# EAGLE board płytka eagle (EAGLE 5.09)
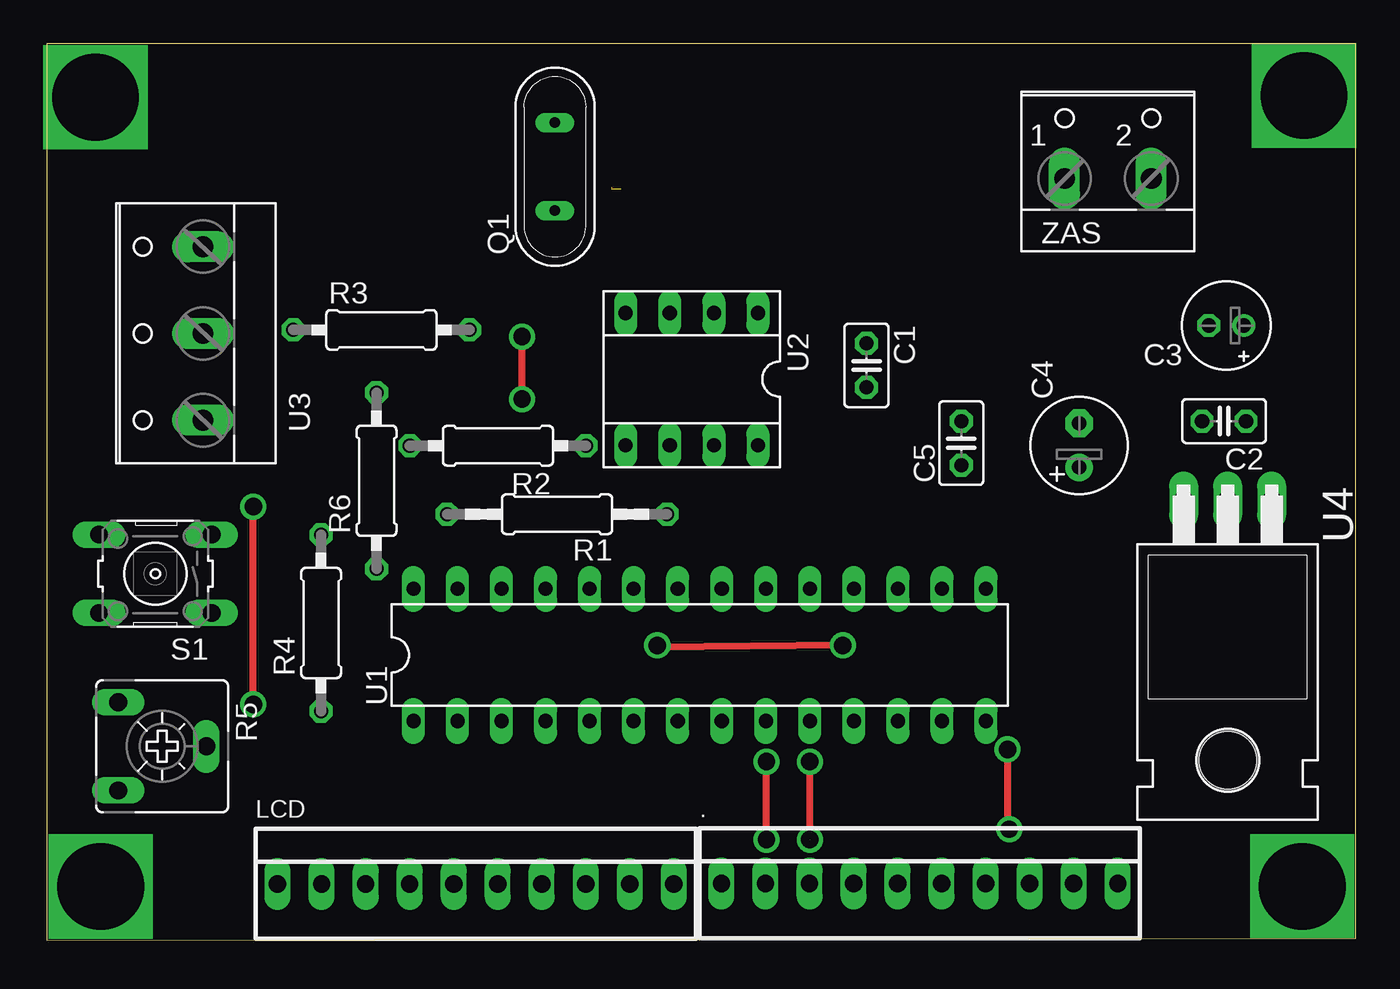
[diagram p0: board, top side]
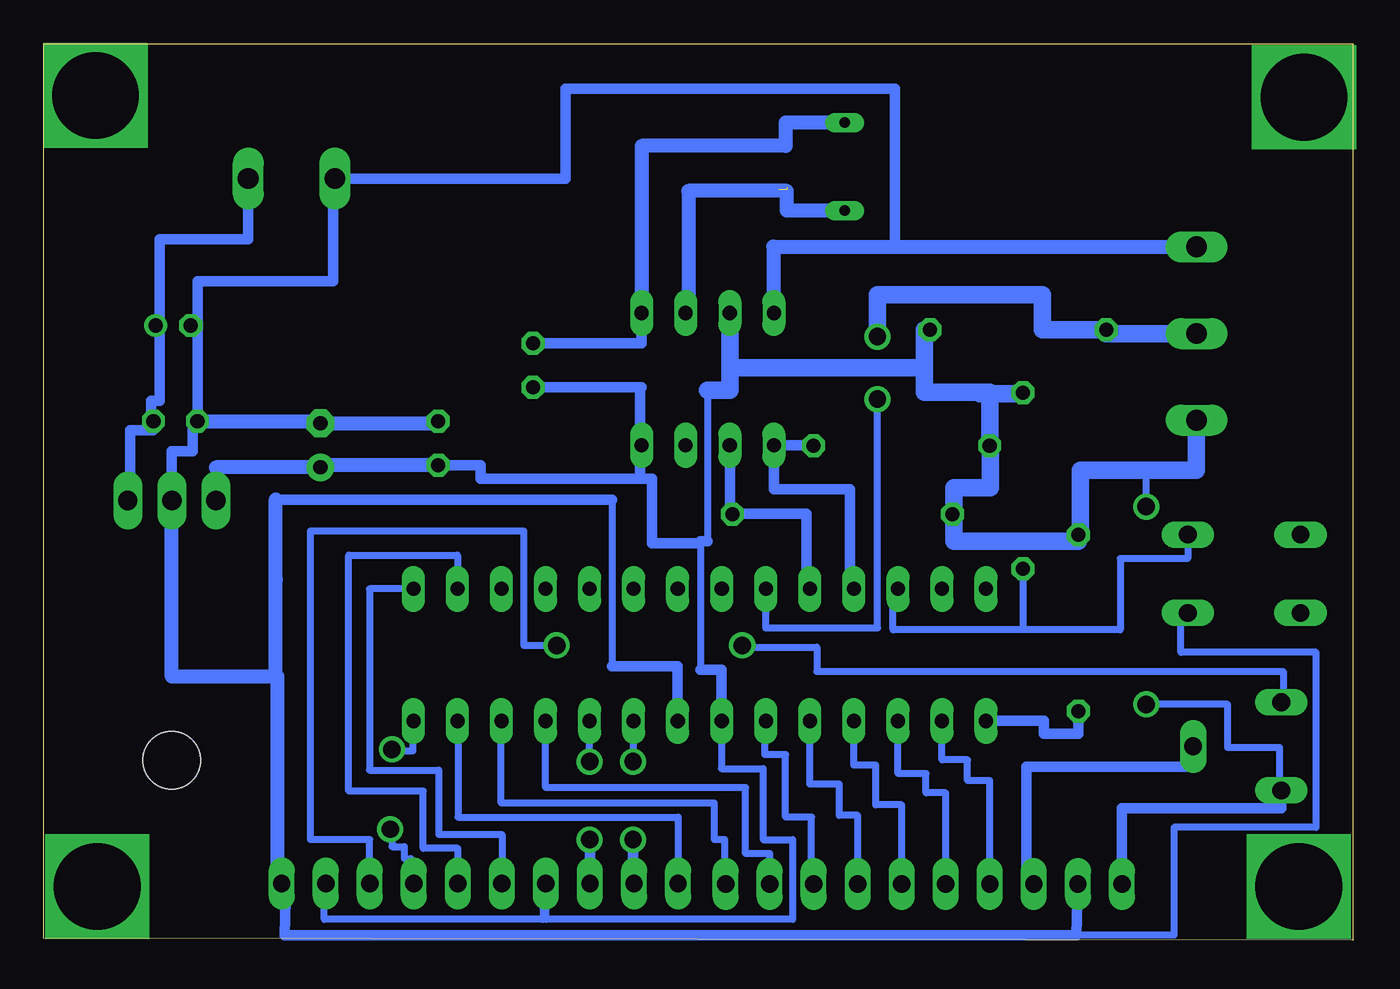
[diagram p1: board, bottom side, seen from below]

Size 75.5 x 51.7 mm. Coordinates in mm from the lower left corner, seen from the top.
Outline: 0,0 75.5,0.1 75.5,51.7 0,51.7 0,0
Copper layers (1*16): Top 0.035mm / dielectric 1.5mm / Bottom 0.035mm
Design rules "default": minimum track width 10mil, minimum drill 24mil, track to track 8mil, track to pad 8mil, pad to pad 8mil, via to via 8mil, smd to smd 8mil, copper to edge 40mil, drill to drill 8mil, minimum pad ring 10mil, minimum via ring 8mil, stop-mask expansion 4mil, vias tented up to drill 0mil, thermal gap 10mil

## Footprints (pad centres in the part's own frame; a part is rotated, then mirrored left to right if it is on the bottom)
22-23-2101 = drill 1 long: 1 -11.43,0; 2 -8.89,0; 3 -6.35,0; 4 -3.81,0; 5 -1.27,0; 6 1.27,0; 7 3.81,0; 8 6.35,0; 9 8.89,0; 10 11.43,0
C025-025X050 = drill 0.813 octagon: 1 -1.27,0; 2 1.27,0
E2-5 = drill 0.813 pad 1.27 round: + -1.016,0 | drill 0.813 pad 1.27 octagon: - 1.016,0
E2,5-6 = drill 0.813 pad 1.6 round: + -1.27,0 | drill 0.813 pad 1.6 octagon: - 1.27,0
QS = drill 0.61 long: 1 -2.54,0; 2 2.54,0
0207/12 = drill 0.813 octagon: 1 -6.35,0; 2 6.35,0
0207/10 = drill 0.813 octagon: 1 -5.08,0; 2 5.08,0
CA6V = drill 1.016 long: A -2.54,-2.54; E 2.54,-2.54; S 0,2.54
B3F-10XX = drill 1.016 long: 1 -3.251,2.261; 2 3.251,2.261; 3 -3.251,-2.261; 4 3.251,-2.261
DIL28-3 = drill 0.813 long: 1 -16.51,-3.81; 2 -13.97,-3.81; 3 -11.43,-3.81; 4 -8.89,-3.81; 5 -6.35,-3.81; 6 -3.81,-3.81; 7 -1.27,-3.81; 8 1.27,-3.81; 9 3.81,-3.81; 10 6.35,-3.81; 11 8.89,-3.81; 12 11.43,-3.81; 13 13.97,-3.81; 14 16.51,-3.81; 15 16.51,3.81; 16 13.97,3.81; 17 11.43,3.81; 18 8.89,3.81; 19 6.35,3.81; 20 3.81,3.81; 21 1.27,3.81; 22 -1.27,3.81; 23 -3.81,3.81; 24 -6.35,3.81; 25 -8.89,3.81; 26 -11.43,3.81; 27 -13.97,3.81; 28 -16.51,3.81
SOCKET-08 = drill 0.813 long: 1 -3.81,-3.81; 2 -1.27,-3.81; 3 1.27,-3.81; 4 3.81,-3.81; 5 3.81,3.81; 6 1.27,3.81; 7 -1.27,3.81; 8 -3.81,3.81
W237-103 = drill 1.194 long: 1 -5,-1.29; 2 0,-1.29; 3 5,-1.29
TO220H = drill 1.118 long: 1 -2.54,-10.16; 2 0,-10.16; 3 2.54,-10.16 | hole 3.302: 0,4.826
W237-102 = drill 1.194 long: 1 -2.5,-1.27; 2 2.5,-1.27

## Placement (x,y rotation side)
.  [22-23-2101]  50.33,3.28 0 top
C1  [C025-025X050]  47.27,33.14 270 top
C2  [C025-025X050]  67.89,29.93 180 top
C3  [E2-5]  68.02,35.44 180 top
C4  [E2,5-6]  59.53,28.53 90 top
C5  [C025-025X050]  52.73,28.66 90 top
LCD  [22-23-2101]  24.73,3.25 0 top
Q1  [QS]  29.3,44.6 90 top
R1  10K  [0207/12]  29.42,24.56 180 top
R2  10K  [0207/10]  26.01,28.51 180 top
R3  10K  [0207/10]  19.29,35.19 0 top
R4  10K  [0207/10]  15.81,18.29 90 top
R5  10k  [CA6V]  6.65,11.18 270 top
R6  10K  [0207/10]  19.01,26.49 90 top
S1  [B3F-10XX]  6.25,21.13 180 top
U1  [DIL28-3]  37.65,16.45 0 top
U2  [SOCKET-08]  37.19,32.35 180 top
U3  + syg -  [W237-103]  7.71,34.98 90 top
U4  [TO220H]  68.1,15.2 180 top
ZAS  [W237-102]  61.19,45.18 0 top

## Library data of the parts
. LCD = con-molex
C1-C5 R1-R4 R6 = rcl
Q1 = special
R5 = pot
S1 = switch-omron
U1 U2 = ic-package
U3 ZAS = con-wago-500
U4 = linear

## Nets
AAA: ..8 R5.A
C1: C2.1 C3.+ U4.1 ZAS.2
CS1: ..2 U1.9
CS2: ..3 U1.10
D0: LCD.4 U1.2
D1: LCD.5 U1.3
D2: LCD.6 U1.4
D3: LCD.7 U1.5
D4: LCD.8 U1.6
D5: LCD.9 U1.11
D6: LCD.10 U1.12
D7: ..1 U1.13
E: ..7 U1.14
GND: ..10 C2.2 C3.- C4.- C5.2 LCD.2 S1.1 U1.8 U2.4 U3.3 U4.2 ZAS.1
GUZ: S1.3 U1.26
N$2: R4.1 U1.1
N$3: C1.2
N$4: C1.1 Q1.2 U2.1
N$5: Q1.1 U2.2
N$6: LCD.3 R5.S
RS: ..6 U1.16
RW: ..5 U1.15
SCL: R1.1 U1.24 U2.6
SDA: R2.1 U1.25 U2.5
SYG: R3.1 U1.23 U3.2
VCC: ..4 ..9 C4.+ C5.1 LCD.1 R1.2 R2.2 R3.2 R4.2 R5.E U1.7 U2.3 U3.1 U4.3

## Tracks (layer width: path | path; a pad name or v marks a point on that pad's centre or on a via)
AAA  (via drill 0.6, 1)
  Top 0.406: v45.9,17 v35.2,16.9
  Bottom 0.406: ..8 56.68,5.8 60.1,5.8 60.1,23.6 47.8,23.6 47.8,17 46,17 | 46.2,16.8 46,17 | 46,17 v45.9,17 | v35.2,16.9 30.9,16.9 30.9,15.5 4,15.5 4,13.72 R5.A
C1
  Bottom 0.61: ZAS.2 63.69,40.4 68.8,40.4 68.8,35.44 | 68.8,35.44 C3.+ | 68.8,35.44 68.8,31.1 69.3,31.1 69.3,29.93 C2.1 69.16,29.4 70.5,29.4 70.5,25.36 U4.1
CS1  (via drill 0.6)
  Top 0.406: v41.5,5.8 v41.5,10.3
  Bottom 0.406: U1.9 41.46,10.3 v41.5,10.3
  Bottom 0.61: v41.5,5.8 41.5,3.28 ..2
CS2  (via drill 0.6)  (1 unrouted)
  Top 0.406: 44,5.8 v44,10.3
  Bottom 0.406: v44,10.3 U1.10
  Bottom 0.61: ..3 43.98,5.8 44,5.8
D0
  Bottom 0.406: 23.7,12.64 U1.2 23.68,10.4 22.2,10.4 22.2,9.2 20.92,9.2 LCD.4
D1
  Bottom 0.406: 26.2,12.64 U1.3 26.22,9.6 24.6,9.6 24.6,8.5 23.46,8.5 LCD.5
D2
  Bottom 0.406: 28.8,12.64 U1.4 28.76,10.1 27.5,10.1 27.5,7.8 26,7.8 LCD.6
D3
  Bottom 0.406: LCD.7 28.54,7.2 29.6,7.2 29.6,9 31.3,9 U1.5
D4
  Bottom 0.406: U1.6 33.9,12.64 33.9,10.7 32.7,10.7 32.7,7.1 31.2,7.1 31.2,3.25 LCD.8
D5
  Bottom 0.406: LCD.9 33.6,3.25 33.6,5 35,5 35,8.8 46.54,8.8 U1.11
D6
  Bottom 0.406: U1.12 49.1,12.64 49.1,7.9 36.8,7.9 36.8,5.8 36.2,5.8 36.2,3.25 LCD.10
D7
  Bottom 0.406: U1.13 51.6,12.64 51.6,7.1 38.9,7.1 ..1
E  (via drill 0.6)
  Top 0.406: v55.4,10.9 v55.4,6.4
  Bottom 0.406: U1.14 54.2,12.64 54.2,10.9 v55.4,10.9 | v55.4,6.4 55.4,5.4 54.7,5.4 54.7,4.7 54.3,4.7 54.3,3.28 ..7
GND
  Bottom 0.406: 42.7,25.4 42.7,15.8 | S1.1 9.5,18.8 9.7,18.8 9.7,18.9 9.9,18.9 9.9,18.8 | 9.9,18.8 9.4,18.8 | 33.38,39.98 U2.4 33.38,36.3 33.6,36.3 33.6,36.2 33.4,36.2 33.4,35.9 | 9.9,18.8 9.9,16.6 2.1,16.6 2.1,6.5 10.3,6.5 10.3,0.3 16.5,0.3 | 26.4,40 33.4,40
  Bottom 0.61: U4.2 68.1,28.2 66.9,28.2 66.9,29.93 C2.2 66.62,35.44 | 66.62,35.44 C3.- | 66.62,35.44 66.62,38 58.8,38 58.8,43.61 ZAS.1 45.4,43.91 45.4,49.1 26.4,49.1 26.4,40 | 52.73,29.8 C5.2 52.73,30 52.9,30 52.9,29.9 | 62,3.28 ..10 61.5,3.28 61.6,0.3 16.5,0.3 15.94,0.3 LCD.2 | 52.9,29.9 52.6,29.9 | U2.4 33.38,36.2 33.3,36.2 | U1.8 38.92,15.8 42.7,15.8 | 62.1,25.4 42.7,25.4 | 52.9,29.8 52.9,29.9 | 59.53,29.93 C4.- | 62.1,15.2 62.3,15.1 62.3,15.2 62.1,15.2
  Bottom 0.813: U4.2 68.1,15.2 62.3,15.2 | 62,3.28 62,15.2 62.1,15.2 62.1,20.8 62.1,25.4 | 33.38,39.98 U3.3 | 33.4,40 33.4,36.2 | C4.- 52.9,29.8 | C2.2 59.53,29.93
GUZ
  Bottom 0.406: S1.3 9.5,22 13.4,22 13.4,17.9 26.5,17.9 26.5,20.26 U1.26
N$1  (via drill 5)
  other vias: 3.1,3.1
N$2
  Bottom 0.61: R4.1 15.81,11.9 17.8,11.9 17.8,12.64 U1.1
N$3
  Bottom 0.61: 41,31.87 C1.2
N$4
  Bottom 0.61: 32.7,45.8 32.62,45.8 | U2.1 41,34.41 C1.1
  Bottom 0.813: U2.1 41,45.8 32.7,45.8 32.7,47.14 Q1.2
N$5
  Bottom 0.61: 38.3,36.16 U2.2
  Bottom 0.813: 38.3,36.16 38.3,43.2 32.62,43.2 32.62,42.06 Q1.1
N$6
  Bottom 0.61: R5.S 9.19,10 18.8,10 18.8,3.25 LCD.3
N$7  (via drill 5)
  other vias: 72.4,3.1
N$8  (via drill 5)
  other vias: 2.8,48.6
N$9  (via drill 5)
  other vias: 72.5,48.7
N$10  (via drill 1)
  other vias: 41.5,10.3
N$11  (via drill 1)
  other vias: 44,10.3
N$12  (via drill 1)
  other vias: 41.5,5.8
N$13  (via drill 1)
  other vias: 44,5.8
N$14  (via drill 1)
  other vias: 55.5,6.4
N$15  (via drill 1)
  other vias: 55.4,11
N$16  (2 unrouted)
N$17  (via drill 1)
  other vias: 27.4,31.2
N$18  (via drill 1)
  other vias: 35.2,17
N$19  (via drill 1)
  other vias: 27.4,34.8
N$20  (via drill 1)
  other vias: 11.9,13.6
N$21  (via drill 1)
  other vias: 11.9,25
RS
  Bottom 0.406: ..6 51.6,5.3 53.6,5.3 53.6,8.6 57.9,8.6 57.9,22.2 51.62,22.2 U1.16
RW
  Bottom 0.406: U1.15 56.7,20.26 56.7,9.8 52.7,9.8 52.7,6.1 49.06,6.1 ..5
S$1
  Bottom 0.406: 41,31.6 41,31.7 41.1,31.7
  Bottom 0.61: 41.1,26.7 41.1,30.3 41.1,31.7
S$2
  Bottom 0.406: 19,21.4 19,18
SCL
  Bottom 0.61: U1.24 31.5,20.26 31.5,24.6 35.77,24.6 R1.1 35.92,24.56 U2.6
SDA
  Bottom 0.61: U1.25 29,20.26 29,26 33.38,26 U2.5 31.09,28.54 R2.1
SYG  (via drill 0.6)
  Top 0.406: v27.4,31.3 v27.4,34.8 27.5,34.8
  Bottom 0.406: U1.23 33.84,18 27.4,18 v27.4,31.3 | R3.1 14.21,34.98
  Bottom 1.016: v27.4,34.8 27.4,37.2 17.9,37.2 17.9,35.19 R3.1 | 14.21,34.98 U3.2
VCC  (via drill 0.6)
  Top 0.406: v11.9,13.6 v11.9,25
  Bottom 0.406: ..4 46.6,3.28 46.6,3.3 | 46.6,3.4 46.7,3.4 46.7,1.2 59.3,1.2 59.3,3.28 ..9 | 37.2,31.7 37.2,23 | 37.6,22.9 37.6,15.6 | 15.7,23.37 R4.2 15.81,23 | 23,24.56 R1.2 | 20.9,28.51 R2.2 | 13.3,7.6 4,7.6 4,8.3 4.2,8.3 4.2,11.1 7.2,11.1 7.2,13.6 v11.9,13.6 | v11.9,25 11.9,27.1 | 46.5,3.5 46.5,1.2 32.3,1.2 32.3,5.8 34,5.8 34,9.9 36.4,9.9 36.4,12.64 | 21.5,31.5 21.5,31.6 | 24.7,35.19 R3.2 24.7,35.2 24.7,35.19
  Bottom 0.61: 37.2,23 37.6,23 37.6,22.9 40.4,22.9 40.4,26.6 50.3,26.6 50.3,27.39 C5.1 | 37.6,15.6 36.4,15.6 36.4,13 | U1.7 36.4,12.64 36.4,13 | 36.4,13 36.3,13 36.3,12.9 36.6,12.9 | 65.56,27.26 U4.3 | 59.53,27.39 C4.+ | R5.E 4.11,7.6 13.3,7.6 LCD.1 | 46.6,3.3 46.6,3.4 46.6,3.5 46.5,3.5
  Bottom 0.813: C4.+ 65.56,27.26 | C5.1 59.53,27.39
  Bottom 1.016: 35.92,33 35.92,31.7 37.2,31.7 | 35.92,33 U2.3 | U3.1 9,27.1 11.9,27.1 15.7,27.1 15.7,23.37 | 15.81,23 23,23 23,24.56 23,26.1 20.9,26.1 20.9,28.51 | R2.2 20.93,31.6 21.5,31.6 24.7,31.6 24.7,33 | 24.7,33 24.7,35.19 | 24.7,33 35.92,33 | 19.1,31.5 21.5,31.5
